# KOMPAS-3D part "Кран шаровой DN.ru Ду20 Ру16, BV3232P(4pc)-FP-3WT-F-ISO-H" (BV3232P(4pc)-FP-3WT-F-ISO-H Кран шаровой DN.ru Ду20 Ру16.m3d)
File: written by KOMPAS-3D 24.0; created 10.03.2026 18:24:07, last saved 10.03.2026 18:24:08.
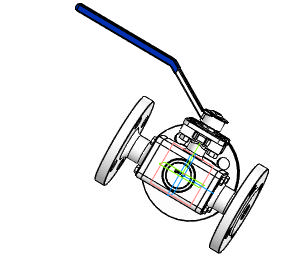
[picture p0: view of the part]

Document properties: Автор: R2D2; Полное имя файла: E:\Работа\Зайцев\BV3232P(4pc)-FP-3WT-F-ISO-H Кран шаровой DN.ru Ду15-100 Ру16\DN20\BV3232P(4pc)-FP-3WT-F-ISO-H Кран шаровой DN.ru Ду20 Ру16.m3d

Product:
- Part/product: Кран шаровой DN.ru Ду20 Ру16  | designation BV3232P(4pc)-FP-3WT-F-ISO-H
    Масса: 4.5
    Раздел спецификации: Прочие изделия
    Примечание: D160-36347

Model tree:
1. Операция без истории:1

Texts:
  BV3232P(4pc)-FP-3WT-F-ISO-H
